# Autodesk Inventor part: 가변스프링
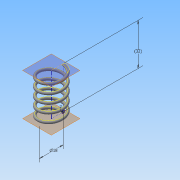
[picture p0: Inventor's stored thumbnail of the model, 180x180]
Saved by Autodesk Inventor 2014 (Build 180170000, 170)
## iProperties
Created: 2017-12
Part Number: 가변스프링
Material: 일반
Document SubType Name: Modeling
Designer: 학생용
Mass: 0.874971 g
Surface Area: 17.755 cm^2
Volume: 0.874971 cm^3
Density: 1 g/cm^3
Appearance: 기본값
Author: 학생용
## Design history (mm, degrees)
sketch "스케치1"
  geometry: L1 (0, 0)-(28.5, 0); L2 (28.5, 0)-(28.5, -9); L3 (28.5, -9)-(0, -9); L4 (0, -9)-(0, 0); C1 r 1 at (0, -9)
  constraints: 8 end point, 2 parallel, 1 centre point, 1 coincident, 1 horizontal, 1 perpendicular
  dimensions: "d0" = 28.5 distance between parallel lines of L4 L2 (derived); "d1" = 2 diameter of C1; "d2" = 18 diameter of L3 L1
feature "코일1" sketch "스케치1" pitch "d3" = 10; turns "d5" = 5; dims "d4" = 28.5 (= d0), "d6" = 0, angle "d7" = 90 deg, angle "d8" = 90 deg, "d9" = 0, "d10" = 0
node "작업 평면1"
node "작업 평면2"
sketch "스케치2"
  geometry: L1 (0, -10)-(0, -8) reference; 2 further points
  constraints: 2 other
extrude "돌출1" cut sketch "스케치2" distance "d11" = 10; taper "d12" = 0 deg
sketch "스케치3"
  geometry: L1 (0, -10)-(0, -8) reference; 1 further point
  constraints: 1 vertical alignment
extrude "돌출2" cut sketch "스케치3" distance "d13" = 10; taper "d14" = 0 deg
node "솔리드1"
node "절단 모서리 투영1"
node "절단 모서리 투영2"
